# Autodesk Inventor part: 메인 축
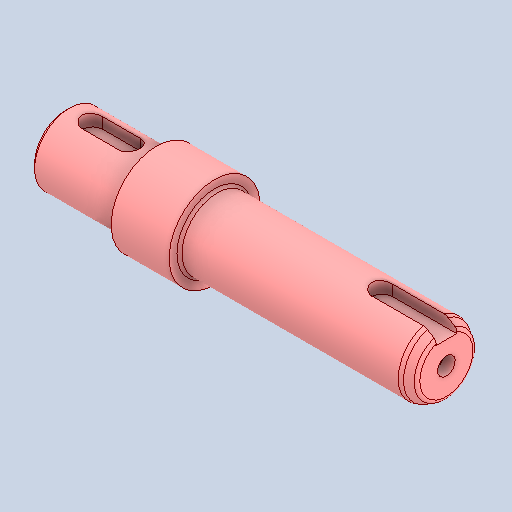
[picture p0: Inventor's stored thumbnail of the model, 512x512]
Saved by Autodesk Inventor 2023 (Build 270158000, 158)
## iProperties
Created: 2025-04
Part Number: 메인 축
Material: 강철, 탄소
Document SubType Name: Modeling
Designer: User
Density: 7.85 g/cm^3
Appearance: 기본값
Author: jhkim
Sending System: Autodesk Inventor 2026
Preprocessor: ST-DEVELOPER v20.1
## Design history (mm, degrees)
feature "솔리드1"
node "솔리드2"
